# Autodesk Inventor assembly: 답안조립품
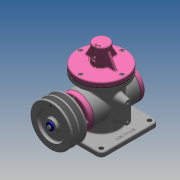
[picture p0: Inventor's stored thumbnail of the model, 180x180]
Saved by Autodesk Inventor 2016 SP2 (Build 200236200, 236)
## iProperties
Created: 2020-02
Part Number: 답안조립품
Document SubType Name: Assembly
Designer: EZ
Author: EZ
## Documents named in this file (21)
- X:\600206V1027 최호선\600206V1027\답안조립품.iam
- X:\600206V1027 최호선\600206V1027\본체.ipt
- X:\600206V1027 최호선\600206V1027\E-링.ipt
- X:\600206V1027 최호선\600206V1027\V-벨트풀리.ipt
- X:\600206V1027 최호선\600206V1027\가변스프링.ipt
- X:\600206V1027 최호선\600206V1027\개스킷 A.ipt
- X:\600206V1027 최호선\600206V1027\개스킷 B.ipt
- X:\600206V1027 최호선\600206V1027\덮개.ipt
- X:\600206V1027 최호선\600206V1027\뒤커버.ipt
- X:\600206V1027 최호선\600206V1027\링크.ipt
- X:\600206V1027 최호선\600206V1027\베어링 17 x 40 x 12.ipt
- X:\600206V1027 최호선\600206V1027\볼트 M4 x 10.ipt
- X:\600206V1027 최호선\600206V1027\슬라이더.ipt
- X:\600206V1027 최호선\600206V1027\앞커버.ipt
- X:\600206V1027 최호선\600206V1027\오일 실 17 30 8.ipt
- X:\600206V1027 최호선\600206V1027\와셔 4x16.ipt
- X:\600206V1027 최호선\600206V1027\육각 소켓 머리 볼트 M4 x 10.ipt
- X:\600206V1027 최호선\600206V1027\클레비스 핀 6 x 22.ipt
- 클레비스 핀 6 x 22.ipt
- X:\600206V1027 최호선\600206V1027\키 4 x 4 x 25.ipt
- X:\600206V1027 최호선\600206V1027\편심축.ipt
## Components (6 placed, 5 different names)
1. E-링:1 — 각도:4
2. V-벨트풀리:1 — 각도:2
3. 가변스프링:1
4. 개스킷 A:1
5. 개스킷 B:1
6. 개스킷 A:2
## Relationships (2: Angle 2)
- 각도:2 [Angle]: V-벨트풀리:1
- 각도:4 [Angle]: E-링:1
